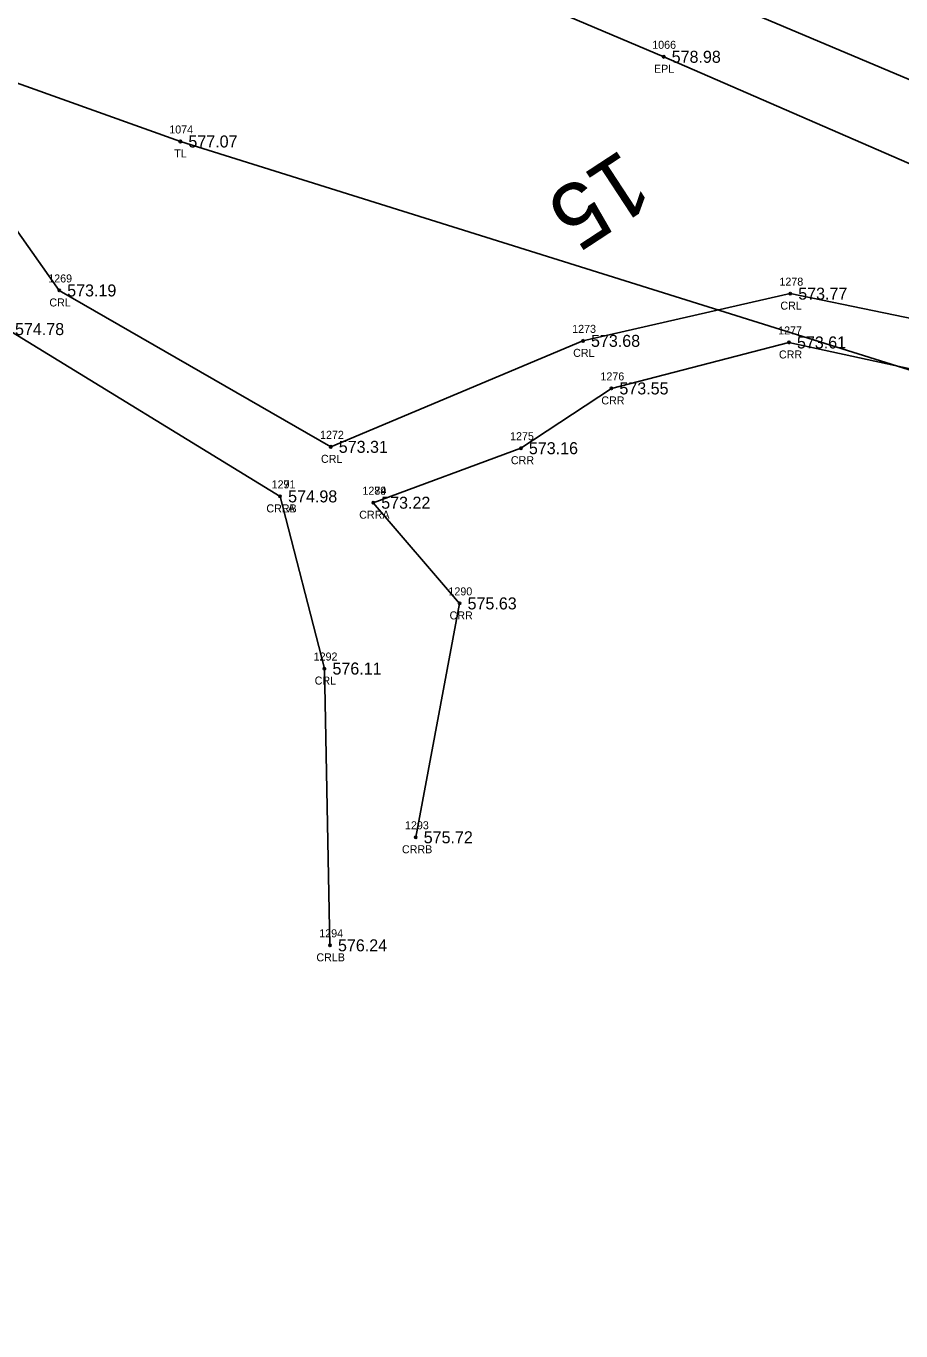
# Model space of a CAD drawing. Extents: x 1664393 to 1667175, y 987029 to 988607.
# Drawn here: x 1665523.9 to 1665633.2, y 987555.5 to 987718.5 of the extents above; entities that cross this region are included whole.
import ezdxf

# ---------------------------------------------------------------- set-up
doc = ezdxf.new("R2010")
doc.units = 0
for name, color, linetype in [('RD_EX_H2O', 7, 'Continuous'), ('RD_EX_H2O_txCode', 7, 'Continuous'), ('RD_EX_Road', 7, 'Continuous'), ('RD_EX_Road_txCode', 7, 'Continuous'), ('RD_EX_TX_H2O_ELEV', 7, 'Continuous'), ('RD_EX_TX_Road_ELEV', 7, 'Continuous'), ('RD_EX_TX_VEG_ELEV', 7, 'Continuous'), ('RD_EX_VEG', 7, 'Continuous'), ('RD_EX_VEG_txCode', 7, 'Continuous'), ('RD_HC_Cl', 7, 'Continuous'), ('RD_HC_TX_Sta50', 7, 'Continuous'), ('RD_SMD_Locator', 7, 'Continuous')]:
    doc.layers.add(name, color=color, linetype=linetype)

msp = doc.modelspace()

# ---------------------------------------------------------------- linework, layer by layer
at = {"layer": 'RD_EX_H2O'}
for points in [[(1665565.69, 987792.78), (1665555.48, 987787.59), (1665542.58, 987772.17), (1665532.86, 987767.81), (1665532.86, 987767.81), (1665523.69, 987745.83), (1665522.12, 987740.87), (1665518.2, 987735.79), (1665482.82, 987708), (1665483.87, 987700.87), (1665513.49, 987706.09), (1665528.04, 987685.52), (1665561.97, 987665.98), (1665593.48, 987679.22), (1665619.37, 987685.12), (1665642.78, 987680.31), (1665663.97, 987651.85), (1665686.03, 987634.26), (1665705.62, 987627.98), (1665724.83, 987594.97)], [(1665465.98, 987698.59), (1665486.18, 987692.85), (1665509.53, 987698.53), (1665521.52, 987680.69), (1665555.64, 987659.79)], [(1665567.27, 987659), (1665585.72, 987665.81), (1665597.03, 987673.28), (1665619.21, 987679.02), (1665636.86, 987675.2), (1665656.96, 987646.24), (1665680.5, 987626.23), (1665698.55, 987621.97), (1665717.6, 987587.14)], [(1665555.64, 987659.79), (1665561.18, 987638.28), (1665561.87, 987603.7)], [(1665567.27, 987659), (1665578.06, 987646.42), (1665572.58, 987617.2)]]:
    msp.add_lwpolyline(points, dxfattribs=at)
at = {"layer": 'RD_EX_Road'}
msp.add_lwpolyline([(1666156.67, 987480.61), (1666109.28, 987500.74), (1666063.55, 987520.04), (1666017.04, 987539.82), (1665971.11, 987559.14), (1665924.88, 987578.79), (1665879.5, 987597.89), (1665833.22, 987617.38), (1665786.91, 987636.81), (1665741.44, 987656.13), (1665695.81, 987675.2), (1665649.26, 987694.85), (1665603.56, 987714.71), (1665558.4, 987733.87), (1665524.71, 987748.93)], dxfattribs=at)
at = {"layer": 'RD_EX_VEG'}
msp.add_lwpolyline([(1666150.2, 987465.22), (1665963.16, 987547.12), (1665727.12, 987646.51), (1665543.18, 987704.13), (1665449.91, 987737.53), (1665163.85, 987870.35), (1665156.07, 987854.03)], dxfattribs=at)
at = {"layer": 'RD_HC_Cl'}
msp.add_line((1666160.05, 987489.41), (1664963.07, 987995.8), dxfattribs=at)
at = {"layer": 'RD_SMD_Locator'}
for centre in [(1665603.56, 987714.71), (1665543.18, 987704.13), (1665528.04, 987685.52), (1665619.37, 987685.12), (1665593.48, 987679.22), (1665619.21, 987679.02), (1665597.03, 987673.28), (1665561.97, 987665.98), (1665585.72, 987665.81), (1665555.64, 987659.79), (1665555.64, 987659.79), (1665567.27, 987659), (1665567.27, 987659), (1665578.06, 987646.42), (1665561.18, 987638.28), (1665572.58, 987617.2), (1665561.87, 987603.7)]:
    msp.add_circle(centre, 0.15, dxfattribs=at)

# ---------------------------------------------------------------- texts
at = {"layer": 'RD_EX_H2O_txCode'}
for s, p in [('1269', (1665526.67, 987686.52)), ('1278', (1665618.02, 987686.12)), ('CRL', (1665526.81, 987683.52)), ('CRL', (1665618.14, 987683.12)), ('1273', (1665592.13, 987680.22)), ('1277', (1665617.86, 987680.02)), ('CRL', (1665592.25, 987677.22)), ('CRR', (1665617.96, 987677.02)), ('1276', (1665595.66, 987674.28)), ('CRR', (1665595.77, 987671.28)), ('1272', (1665560.63, 987666.98)), ('1275', (1665584.37, 987666.81)), ('CRL', (1665560.74, 987663.98)), ('CRR', (1665584.47, 987663.81)), ('1271', (1665554.58, 987660.79)), ('1291', (1665554.58, 987660.79)), ('1274', (1665565.92, 987660)), ('1289', (1665565.92, 987660)), ('CRRB', (1665553.92, 987657.79)), ('CRLA', (1665553.93, 987657.79)), ('CRRA', (1665565.52, 987657)), ('CRRA', (1665565.52, 987657)), ('1290', (1665576.67, 987647.42)), ('CRR', (1665576.81, 987644.42)), ('1292', (1665559.83, 987639.28)), ('CRL', (1665559.95, 987636.28)), ('1293', (1665571.24, 987618.2)), ('CRRB', (1665570.86, 987615.2)), ('1294', (1665560.53, 987604.7)), ('CRLB', (1665560.17, 987601.7))]:
    msp.add_text(s, height=1, dxfattribs=at).set_placement(p)
at = {"layer": 'RD_EX_Road_txCode'}
for s, p in [('1066', (1665602.13, 987715.71)), ('EPL', (1665602.35, 987712.71))]:
    msp.add_text(s, height=1, dxfattribs=at).set_placement(p)
at = {"layer": 'RD_EX_TX_H2O_ELEV'}
for s, p in [('573.19', (1665529.04, 987684.77)), ('573.77', (1665620.37, 987684.37)), ('574.78', (1665522.52, 987679.94)), ('573.68', (1665594.48, 987678.47)), ('573.61', (1665620.21, 987678.27)), ('573.55', (1665598.03, 987672.53)), ('573.31', (1665562.97, 987665.23)), ('573.16', (1665586.72, 987665.06)), ('574.98', (1665556.64, 987659.04)), ('574.98', (1665556.64, 987659.04)), ('573.22', (1665568.27, 987658.25)), ('573.22', (1665568.27, 987658.25)), ('575.63', (1665579.06, 987645.67)), ('576.11', (1665562.18, 987637.53)), ('575.72', (1665573.58, 987616.45)), ('576.24', (1665562.87, 987602.95))]:
    msp.add_text(s, height=1.5, dxfattribs=at).set_placement(p)
at = {"layer": 'RD_EX_TX_Road_ELEV'}
msp.add_text('578.98', height=1.5, dxfattribs=at).set_placement((1665604.56, 987713.96))
at = {"layer": 'RD_EX_TX_VEG_ELEV'}
msp.add_text('577.07', height=1.5, dxfattribs=at).set_placement((1665544.18, 987703.38))
at = {"layer": 'RD_EX_VEG_txCode'}
for s, p in [('1074', (1665541.79, 987705.13)), ('TL', (1665542.41, 987702.13))]:
    msp.add_text(s, height=1, dxfattribs=at).set_placement(p)
at = {"layer": 'RD_HC_TX_Sta50'}
msp.add_text('15', height=8, rotation=213.2247, dxfattribs=at).set_placement((1665598.39, 987703.3))

doc.saveas('drawing.dxf')
